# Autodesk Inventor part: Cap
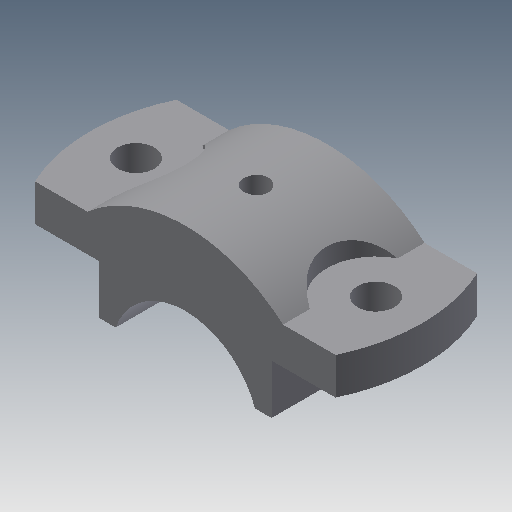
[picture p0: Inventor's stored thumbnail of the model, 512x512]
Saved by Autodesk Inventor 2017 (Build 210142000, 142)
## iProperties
Created: 2009-04
Part Number: Cap
Document SubType Name: Modeling
Designer: Sham
Density: 1 g/cm^3
Material: Generic
Appearance: Default
Mass: 94.0132 g
Surface Area: 184.419 cm^2
Volume: 94.0132 cm^3
Author: Sham
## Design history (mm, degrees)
sketch "Sketch1"
  geometry: L1 (-48.857, 23)-(48.857, 23); L2 (48.857, -23)-(-48.857, -23); A1 r 54 centre (0, 0) between (-48.857, 23) and (-48.857, -23); A2 r 54 centre (0, 0) between (48.857, -23) and (48.857, 23); 1 further point
  constraints: 4 end point, 4 point on circle, 2 centre point, 2 coincident, 1 horizontal, 1 parallel, 1 other
  dimensions: "d3" = 54 radius of A1; "d4" = 54 radius of A2; "d5" = 46 distance between parallel lines of L2 L1; "d6" = 23 distance from line of point (0, 0) L1
extrude "Extrusion1" new body sketch "Sketch1" distance "d7" = 12; taper "d8" = 0 deg
sketch "Sketch3"
  geometry: L1 (20.906, 0)-(20.906, -16); L2 (76.906, -0.137)-(76.906, -16.137); L3 (20.906, -16)-(26.23, -16); L4 (71.532, -16.137)-(76.906, -16.137); L5 (76.906, -0.137)-(76.857, 12); L6 (97.714, 0)-(0, 0) reference; L7 (76.857, 12)-(80.606, 12); L8 (17.108, 12)-(20.906, 12); L9 (20.906, 12)-(20.906, 0); L10 (0, 12)-(97.714, 12) reference; A1 r 24 centre (48.857, -24) between (71.532, -16.137) and (26.23, -16); A2 r 48 centre (48.857, -24) between (80.606, 12) and (17.108, 12); 3 further points
  constraints: 16 end point, 4 point on circle, 3 parallel, 3 perpendicular, 2 centre point, 2 coincident, 2 vertical alignment, 1 collinear, 1 midpoint, 1 vertical, 2 other
  dimensions: "d17" = 48 diameter of A1; "d18" = 16 distance of L1.start L1.end; "d19" = 56 distance between parallel lines of L2 L1; "d21" = 8 vertical distance of A1.centre L1.end; "d22" = 48 radius of A2; "d23" = 0 distance from line of L6 L1.start; "d38" = 31.74902 distance of L7.end point (48.857, 12); "d39" = 28 distance from line of point (48.857, 12) L5
extrude "Extrusion2" join sketch "Sketch3" stored distance "d24" = 12; taper "d25" = 0 deg
sketch "Sketch4"
  geometry: 2 further points
  dimensions: "d26" = 78 distance of point (39, 0) point (-39, 0)
hole "Hole1" sketch "Sketch4" at (-39, 0), (39, 0) diameter "d28" = 12; stored, may be unused: countersink angle "d32" = 90 deg, drill point angle "d34" = 118 deg; dims "d29" = 6, "d30" = 4, "d31" = 2, "d33" = 8
sketch "Sketch5"
  geometry: L1 (-31.749, -23)-(-31.749, 23) reference; L2 (-31.749, 14.263)-(-31.749, -14.263); C1 r 6 at (-39, 0) reference; A1 r 16 centre (-39, 0) between (-31.749, -14.263) and (-31.749, 14.263)
  constraints: 2 end point, 2 point on circle, 1 centre point, 1 coincident, 1 collinear, 1 point on line
  dimensions: "d35" = 16 radius of A1
extrude "Extrusion3" cut sketch "Sketch5" distance "d36" = 12; taper "d37" = 0 deg
mirror "Mirror2"
workplane "Work Plane4"
sketch "Sketch6"
  geometry: L1 (-31.749, 0)-(31.749, 0) reference; 1 further point
  dimensions: "d40" = 23 distance from line of L1 point (0, 23)
hole "Hole2" sketch "Sketch6" at (0, 23) diameter "d41" = 6; stored, may be unused: countersink angle "d45" = 90 deg, drill point angle "d47" = 118 deg; dims "d42" = 6, "d43" = 8, "d44" = 16, "d46" = 8
body "Solid1"
